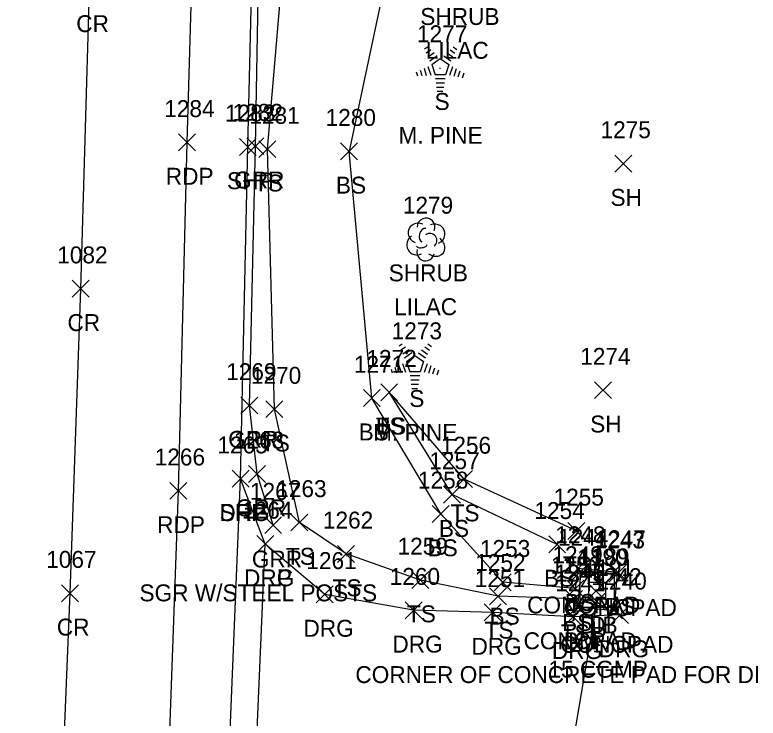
# Model space of a CAD drawing. Extents: x 1618262 to 1622220, y 273782 to 283685.
# Drawn here: x 1622055.1 to 1622142.9, y 282582.4 to 282665.6 of the extents above; entities that cross this region are included whole.
import ezdxf

# ---------------------------------------------------------------- set-up
doc = ezdxf.new("R2010")
doc.units = 0
for name, color, linetype in [('C_A', 7, 'Continuous'), ('C_C', 7, 'Continuous'), ('C_I', 7, 'Continuous'), ('CPBM', 7, 'Continuous'), ('D_A', 7, 'Continuous'), ('D_C', 7, 'Continuous'), ('D_I', 7, 'Continuous'), ('D_TIC', 7, 'Continuous'), ('DCP', 7, 'Continuous'), ('DS', 7, 'Continuous'), ('L_A', 7, 'Continuous'), ('L_C', 7, 'Continuous'), ('L_I', 7, 'Continuous'), ('L_TIC', 7, 'Continuous'), ('LELB', 7, 'Continuous'), ('LS', 7, 'Continuous'), ('LSH', 7, 'Continuous'), ('LTC', 7, 'Continuous'), ('P_A', 7, 'Continuous'), ('P_I', 7, 'Continuous'), ('P_TIC', 7, 'Continuous'), ('PET', 7, 'Continuous'), ('PRC', 7, 'Continuous'), ('PSP', 7, 'Continuous'), ('R_A', 7, 'Continuous'), ('R_C', 7, 'Continuous'), ('R_I', 7, 'Continuous'), ('R_TIC', 7, 'Continuous'), ('RDG', 7, 'Continuous'), ('RDP', 7, 'Continuous'), ('RGR', 7, 'Continuous')]:
    doc.layers.add(name, color=color, linetype=linetype)

msp = doc.modelspace()

# ---------------------------------------------------------------- linework, layer by layer
at = {"layer": 'CPBM'}
for p, q in [((1622121.111, 282595.082), (1622121.111, 282596.082)), ((1622121.111, 282596.082), (1622122.111, 282596.082)), ((1622121.614, 282595.582), (1622121.614, 282595.582)), ((1622121.614, 282595.582), (1622121.614, 282595.582)), ((1622122.111, 282596.082), (1622122.111, 282595.082)), ((1622122.111, 282595.082), (1622121.111, 282595.082))]:
    msp.add_line(p, q, dxfattribs=at)
at = {"layer": 'D_TIC'}
for points in [[(1622122.731, 282596.449), (1622124.731, 282598.449)], [(1622124.731, 282596.449), (1622122.731, 282598.449)], [(1622122.826, 282595.221), (1622124.826, 282597.221)], [(1622124.826, 282595.221), (1622122.826, 282597.221)]]:
    msp.add_lwpolyline(points, dxfattribs=at)
at = {"layer": 'DCP'}
msp.add_lwpolyline([(1622123.826, 282596.221), (1622105.825, 282490.473)], dxfattribs=at)
at = {"layer": 'DS'}
for p, q in [((1622121.872, 282599.503), (1622125.872, 282599.503)), ((1622121.872, 282595.503), (1622121.872, 282599.503)), ((1622125.872, 282599.503), (1622125.872, 282595.503)), ((1622122.872, 282596.503), (1622122.872, 282598.503)), ((1622122.872, 282598.503), (1622124.872, 282598.503)), ((1622124.872, 282598.503), (1622124.872, 282596.503)), ((1622123.877, 282597.504), (1622123.877, 282597.504)), ((1622123.877, 282597.504), (1622123.877, 282597.504)), ((1622124.872, 282596.503), (1622122.872, 282596.503)), ((1622125.872, 282595.503), (1622121.872, 282595.503))]:
    msp.add_line(p, q, dxfattribs=at)
at = {"layer": 'L_TIC'}
for points in [[(1622083.898, 282648.699), (1622085.898, 282650.699)], [(1622085.898, 282648.699), (1622083.898, 282650.699)], [(1622093.56, 282648.447), (1622095.56, 282650.447)], [(1622095.56, 282648.447), (1622093.56, 282650.447)], [(1622125.961, 282646.995), (1622127.961, 282648.995)], [(1622127.961, 282646.995), (1622125.961, 282648.995)], [(1622098.291, 282619.965), (1622100.291, 282621.965)], [(1622100.291, 282619.965), (1622098.291, 282621.965)], [(1622098.291, 282619.965), (1622100.291, 282621.965)], [(1622100.291, 282619.965), (1622098.291, 282621.965)], [(1622123.56, 282620.206), (1622125.56, 282622.206)], [(1622125.56, 282620.206), (1622123.56, 282622.206)], [(1622096.247, 282619.269), (1622098.247, 282621.269)], [(1622098.247, 282619.269), (1622096.247, 282621.269)], [(1622084.727, 282617.96), (1622086.727, 282619.96)], [(1622086.727, 282617.96), (1622084.727, 282619.96)], [(1622107.138, 282609.7), (1622109.138, 282611.7)], [(1622109.138, 282609.7), (1622107.138, 282611.7)], [(1622105.732, 282607.863), (1622107.732, 282609.863)], [(1622107.732, 282607.863), (1622105.732, 282609.863)], [(1622104.39, 282605.573), (1622106.39, 282607.573)], [(1622106.39, 282605.573), (1622104.39, 282607.573)], [(1622087.687, 282604.568), (1622089.687, 282606.568)], [(1622089.687, 282604.568), (1622087.687, 282606.568)], [(1622120.414, 282603.561), (1622122.414, 282605.561)], [(1622122.414, 282603.561), (1622120.414, 282605.561)], [(1622118.15, 282601.979), (1622120.15, 282603.979)], [(1622120.15, 282601.979), (1622118.15, 282603.979)], [(1622093.202, 282600.848), (1622095.202, 282602.848)], [(1622095.202, 282600.848), (1622093.202, 282602.848)], [(1622120.607, 282599.11), (1622122.607, 282601.11)], [(1622122.607, 282599.11), (1622120.607, 282601.11)], [(1622120.949, 282598.814), (1622122.949, 282600.814)], [(1622122.949, 282598.814), (1622120.949, 282600.814)], [(1622125.271, 282598.502), (1622127.271, 282600.502)], [(1622127.271, 282598.502), (1622125.271, 282600.502)], [(1622125.363, 282598.643), (1622127.363, 282600.643)], [(1622127.363, 282598.643), (1622125.363, 282600.643)], [(1622101.984, 282597.765), (1622103.984, 282599.765)], [(1622103.984, 282597.765), (1622101.984, 282599.765)], [(1622111.715, 282597.493), (1622113.715, 282599.493)], [(1622113.715, 282597.493), (1622111.715, 282599.493)], [(1622120.287, 282596.755), (1622122.287, 282598.755)], [(1622122.287, 282596.755), (1622120.287, 282598.755)], [(1622111.16, 282595.839), (1622113.16, 282597.839)], [(1622113.16, 282595.839), (1622111.16, 282597.839)], [(1622120.158, 282595.521), (1622122.158, 282597.521)], [(1622122.158, 282595.521), (1622120.158, 282597.521)], [(1622120.531, 282594.582), (1622122.531, 282596.582)], [(1622122.531, 282594.582), (1622120.531, 282596.582)], [(1622124.873, 282594.159), (1622126.873, 282596.159)], [(1622126.873, 282594.159), (1622124.873, 282596.159)]]:
    msp.add_lwpolyline(points, dxfattribs=at)
at = {"layer": 'LELB'}
for points in [[(1622121.158, 282596.521), (1622112.16, 282596.839), (1622102.984, 282598.765), (1622094.202, 282601.848), (1622088.687, 282605.568), (1622085.727, 282618.96), (1622084.898, 282649.699), (1622087.596, 282681.102), (1622086.983, 282710.968), (1622088.16, 282744.854), (1622088.43, 282782.064), (1622089.473, 282801.31), (1622094.579, 282809.136), (1622103.227, 282816.892), (1622109.052, 282823.895), (1622118.477, 282854.453), (1622116.353, 282881.374), (1622111.854, 282914.537), (1622109.182, 282938.553)], [(1622099.84, 282674.39), (1622094.56, 282649.447)], [(1622126.363, 282599.643), (1622121.607, 282600.11), (1622121.287, 282597.755), (1622112.715, 282598.493), (1622105.39, 282606.573), (1622097.247, 282620.269), (1622094.56, 282649.447)], [(1622119.15, 282602.979), (1622106.732, 282608.863), (1622099.291, 282620.965)], [(1622121.414, 282604.561), (1622108.138, 282610.7), (1622099.291, 282620.965)]]:
    msp.add_lwpolyline(points, dxfattribs=at)
at = {"layer": 'LS'}
msp.add_lwpolyline([(1622125.873, 282595.159), (1622126.271, 282599.502), (1622121.949, 282599.814), (1622121.531, 282595.582), (1622125.873, 282595.159)], dxfattribs=at)
at = {"layer": 'LSH'}
msp.add_line((1622103.607, 282639.075), (1622103.607, 282639.075), dxfattribs=at)
msp.add_line((1622103.607, 282639.075), (1622103.607, 282639.075), dxfattribs=at)
msp.add_arc((1622103.654, 282640.509), 1.047, 335.52715, 180.95627, dxfattribs=at)
for centre, major_axis, ratio, start_param, end_param in [((1622102.816, 282639.741), (1.21, -0.512), 0.895232, 1.570796, 4.712389), ((1622103.399, 282639.533), (-0.208, -0.792), 0.645439, 3.141593, 6.283185), ((1622104.649, 282639.658), (-1.141, -0.483), 0.949671, 1.570796, 4.712389), ((1622102.524, 282638.366), (0.584, -1.042), 0.959034, 3.141593, 6.283185), ((1622104.107, 282638.908), (-0.5, 0.667), 0.989748, 3.141593, 6.283185), ((1622104.608, 282638.242), (-1.09, 0.792), 0.841452, 1.570796, 4.712389), ((1622103.608, 282637.575), (0.265, 1.061), 0.942809, 1.570796, 4.712389), ((1622103.149, 282638.325), (-0.625, -0.083), 0.423636, 0, 3.141593)]:
    msp.add_ellipse(centre, major_axis=major_axis, ratio=ratio, start_param=start_param, end_param=end_param, dxfattribs=at)
at = {"layer": 'LTC'}
for p, q in [((1622103.47, 282661.546), (1622103.824, 282661.803)), ((1622103.679, 282661.08), (1622104.208, 282661.464)), ((1622106.497, 282661.438), (1622107.046, 282661.039)), ((1622106.868, 282661.786), (1622107.287, 282661.482)), ((1622103.889, 282660.614), (1622104.592, 282661.126)), ((1622104.098, 282660.149), (1622104.977, 282660.787)), ((1622104.323, 282659.694), (1622105.335, 282660.428)), ((1622105.335, 282660.428), (1622106.332, 282659.703)), ((1622105.755, 282660.741), (1622106.564, 282660.152)), ((1622106.126, 282661.089), (1622106.805, 282660.596)), ((1622104.323, 282659.694), (1622104.71, 282658.5)), ((1622106.332, 282659.703), (1622105.94, 282658.5)), ((1622102.502, 282658.825), (1622102.654, 282658.357)), ((1622102.957, 282659.042), (1622103.169, 282658.39)), ((1622103.413, 282659.258), (1622103.684, 282658.423)), ((1622103.868, 282659.474), (1622104.199, 282658.455)), ((1622106.769, 282659.432), (1622106.431, 282658.393)), ((1622107.214, 282659.182), (1622106.926, 282658.297)), ((1622107.658, 282658.932), (1622107.421, 282658.202)), ((1622108.102, 282658.682), (1622107.916, 282658.107)), ((1622105.94, 282658.5), (1622104.71, 282658.5)), ((1622105.902, 282658), (1622104.757, 282658)), ((1622105.818, 282657.5), (1622104.83, 282657.5)), ((1622105.735, 282657), (1622104.903, 282657)), ((1622105.651, 282656.5), (1622104.976, 282656.5)), ((1622100.477, 282626.431), (1622100.832, 282626.688)), ((1622100.687, 282625.965), (1622101.216, 282626.35)), ((1622103.504, 282626.323), (1622104.054, 282625.924)), ((1622103.876, 282626.671), (1622104.295, 282626.367)), ((1622100.897, 282625.5), (1622101.6, 282626.011)), ((1622101.106, 282625.034), (1622101.984, 282625.672)), ((1622101.331, 282624.579), (1622102.342, 282625.313)), ((1622102.342, 282625.313), (1622103.339, 282624.588)), ((1622102.762, 282625.626), (1622103.572, 282625.037)), ((1622103.134, 282625.975), (1622103.813, 282625.481)), ((1622101.331, 282624.579), (1622101.718, 282623.385)), ((1622103.339, 282624.588), (1622102.948, 282623.385)), ((1622099.51, 282623.71), (1622099.662, 282623.242)), ((1622099.965, 282623.927), (1622100.177, 282623.275)), ((1622100.421, 282624.143), (1622100.692, 282623.308)), ((1622100.876, 282624.36), (1622101.207, 282623.34)), ((1622103.777, 282624.317), (1622103.439, 282623.278)), ((1622104.222, 282624.067), (1622103.934, 282623.182)), ((1622104.666, 282623.817), (1622104.429, 282623.087)), ((1622105.11, 282623.567), (1622104.924, 282622.992)), ((1622102.948, 282623.385), (1622101.718, 282623.385)), ((1622102.91, 282622.885), (1622101.765, 282622.885)), ((1622102.826, 282622.385), (1622101.838, 282622.385)), ((1622102.742, 282621.885), (1622101.911, 282621.885)), ((1622102.659, 282621.385), (1622101.984, 282621.385))]:
    msp.add_line(p, q, dxfattribs=at)
at = {"layer": 'P_TIC'}
for points in [[(1622074.404, 282649.493), (1622076.404, 282651.493)], [(1622076.404, 282649.493), (1622074.404, 282651.493)], [(1622081.589, 282648.97), (1622083.589, 282650.97)], [(1622083.589, 282648.97), (1622081.589, 282650.97)], [(1622061.841, 282632.199), (1622063.841, 282634.199)], [(1622063.841, 282632.199), (1622061.841, 282634.199)], [(1622080.734, 282609.733), (1622082.734, 282611.733)], [(1622082.734, 282609.733), (1622080.734, 282611.733)], [(1622073.383, 282608.306), (1622075.383, 282610.306)], [(1622075.383, 282608.306), (1622073.383, 282610.306)], [(1622060.585, 282596.203), (1622062.585, 282598.203)], [(1622062.585, 282596.203), (1622060.585, 282598.203)]]:
    msp.add_lwpolyline(points, dxfattribs=at)
at = {"layer": 'PET'}
msp.add_lwpolyline([(1622055.389, 282357.789), (1622060.735, 282405.546), (1622064, 282439.097), (1622067.385, 282476.749), (1622069.453, 282501.975), (1622071.171, 282531.215), (1622072.586, 282558.991), (1622074.383, 282609.306), (1622075.404, 282650.493), (1622076.38, 282682.885), (1622076.73, 282709.495), (1622076.466, 282742.794), (1622075.649, 282781.747), (1622073.854, 282831.38), (1622072.41, 282861.117), (1622070.969, 282880.709), (1622069.108, 282909.864), (1622067.074, 282934.336)], dxfattribs=at)
at = {"layer": 'PRC'}
msp.add_lwpolyline([(1622043.286, 282360.387), (1622048.896, 282407.643), (1622051.69, 282440.973), (1622055.31, 282477.626), (1622057.865, 282516.742), (1622059.99, 282557.513), (1622061.585, 282597.203), (1622062.841, 282633.199), (1622063.878, 282668.538), (1622064.406, 282708.38), (1622064.503, 282747.028), (1622063.87, 282768.185), (1622062.59, 282807.537), (1622060.956, 282848.034), (1622058.907, 282883.676), (1622055.26, 282933.108)], dxfattribs=at)
at = {"layer": 'PSP'}
msp.add_lwpolyline([(1622063.899, 282356.417), (1622068.955, 282404.452), (1622072.02, 282437.728), (1622074.665, 282475.613), (1622076.635, 282501.43), (1622078.271, 282531.064), (1622079.381, 282546.297), (1622079.58, 282558.785), (1622081.734, 282610.733), (1622082.589, 282649.97), (1622083.395, 282682.719), (1622083.739, 282709.962), (1622083.621, 282744.119), (1622083.448, 282781.355), (1622083.165, 282811.548), (1622082.701, 282831.314), (1622081.46, 282858.351), (1622080.359, 282881.435), (1622078.26, 282910.946), (1622077.134, 282929.735), (1622076.71, 282935.514)], dxfattribs=at)
at = {"layer": 'R_TIC'}
for points in [[(1622082.481, 282649.056), (1622084.481, 282651.056)], [(1622084.481, 282649.056), (1622082.481, 282651.056)], [(1622081.779, 282618.397), (1622083.779, 282620.397)], [(1622083.779, 282618.397), (1622081.779, 282620.397)], [(1622082.68, 282610.3), (1622084.68, 282612.3)], [(1622084.68, 282610.3), (1622082.68, 282612.3)], [(1622080.734, 282609.733), (1622082.734, 282611.733)], [(1622082.734, 282609.733), (1622080.734, 282611.733)], [(1622084.58, 282604.247), (1622086.58, 282606.247)], [(1622086.58, 282604.247), (1622084.58, 282606.247)], [(1622083.651, 282602.022), (1622085.651, 282604.022)], [(1622085.651, 282602.022), (1622083.651, 282604.022)], [(1622083.651, 282602.022), (1622085.651, 282604.022)], [(1622085.651, 282602.022), (1622083.651, 282604.022)], [(1622090.679, 282596.059), (1622092.679, 282598.059)], [(1622092.679, 282596.059), (1622090.679, 282598.059)], [(1622101.188, 282594.189), (1622103.188, 282596.189)], [(1622103.188, 282594.189), (1622101.188, 282596.189)], [(1622110.535, 282593.93), (1622112.535, 282595.93)], [(1622112.535, 282593.93), (1622110.535, 282595.93)], [(1622120.042, 282593.428), (1622122.042, 282595.428)], [(1622122.042, 282593.428), (1622120.042, 282595.428)], [(1622125.565, 282593.637), (1622127.565, 282595.637)], [(1622127.565, 282593.637), (1622125.565, 282595.637)]]:
    msp.add_lwpolyline(points, dxfattribs=at)
at = {"layer": 'RDG'}
msp.add_lwpolyline([(1622126.565, 282594.637), (1622121.042, 282594.428), (1622111.535, 282594.93), (1622102.188, 282595.189), (1622091.679, 282597.059), (1622084.651, 282603.022), (1622081.734, 282610.733)], dxfattribs=at)
at = {"layer": 'RDP'}
msp.add_lwpolyline([(1622079.381, 282546.297), (1622082.212, 282549.998), (1622082.715, 282558.142), (1622084.651, 282603.022)], dxfattribs=at)
at = {"layer": 'RGR'}
msp.add_lwpolyline([(1622085.58, 282605.247), (1622083.68, 282611.3), (1622082.779, 282619.397), (1622083.481, 282650.056), (1622084.103, 282682.868), (1622084.658, 282710.116), (1622084.362, 282744.316), (1622084.303, 282781.106), (1622084.959, 282794.061), (1622087.053, 282807.794)], dxfattribs=at)

# ---------------------------------------------------------------- texts
at = {"layer": 'C_A'}
msp.add_text('BM', height=2, dxfattribs=at).set_placement((1622119.929, 282590.582))
at = {"layer": 'C_C'}
msp.add_text('CORNER OF CONCRETE PAD FOR DI', height=2, dxfattribs=at).set_placement((1622095.299, 282586.582))
at = {"layer": 'C_I'}
msp.add_text('1246', height=2, dxfattribs=at).set_placement((1622118.866, 282598.582))
at = {"layer": 'D_A'}
for s, p in [('DIB', (1622121.834, 282592.449)), ('DI', (1622122.932, 282592.504)), ('P', (1622123.204, 282591.221))]:
    msp.add_text(s, height=2, dxfattribs=at).set_placement(p)
at = {"layer": 'D_C'}
msp.add_text('15 CGMP', height=2, dxfattribs=at).set_placement((1622118.118, 282587.221))
at = {"layer": 'D_I'}
for s, p in [('1190', (1622121.519, 282600.449)), ('1189', (1622121.744, 282600.504)), ('1191', (1622122.267, 282599.221))]:
    msp.add_text(s, height=2, dxfattribs=at).set_placement(p)
at = {"layer": 'L_A'}
for s, p in [('SHRUB', (1622102.973, 282664.384)), ('S', (1622104.66, 282654.338)), ('TS', (1622083.307, 282644.699)), ('BS', (1622093, 282644.447)), ('SH', (1622125.449, 282642.995)), ('SHRUB', (1622099.237, 282634.075)), ('S', (1622101.668, 282619.223)), ('TS', (1622097.7, 282615.965)), ('BS', (1622097.732, 282615.965)), ('SH', (1622123.049, 282616.206)), ('BS', (1622095.688, 282615.269)), ('TS', (1622084.137, 282613.96)), ('TS', (1622106.548, 282605.7)), ('BS', (1622105.173, 282603.863)), ('BS', (1622103.831, 282601.573)), ('TS', (1622087.096, 282600.568)), ('TS', (1622119.823, 282599.561)), ('BS', (1622117.591, 282597.979)), ('TS', (1622092.611, 282596.848)), ('CONCPAD', (1622115.595, 282594.814)), ('CONCPAD', (1622119.917, 282594.502)), ('BS', (1622120.048, 282595.11)), ('BS', (1622124.804, 282594.643)), ('TS', (1622101.394, 282593.765)), ('BS', (1622111.156, 282593.493)), ('BS', (1622119.728, 282592.755)), ('TS', (1622110.57, 282591.839)), ('TS', (1622119.568, 282591.521)), ('CONCPAD', (1622115.176, 282590.582)), ('CONCPAD', (1622119.519, 282590.159))]:
    msp.add_text(s, height=2, dxfattribs=at).set_placement(p)
at = {"layer": 'L_C'}
for s, p in [('LILAC', (1622103.619, 282660.384)), ('M. PINE', (1622100.393, 282650.338)), ('LILAC', (1622099.883, 282630.075)), ('M. PINE', (1622097.401, 282615.223))]:
    msp.add_text(s, height=2, dxfattribs=at).set_placement(p)
at = {"layer": 'L_I'}
for s, p in [('1277', (1622102.582, 282662.338)), ('1281', (1622082.772, 282652.699)), ('1280', (1622091.78, 282652.447)), ('1275', (1622124.268, 282650.995)), ('1279', (1622100.907, 282642.075)), ('1273', (1622099.59, 282627.223)), ('1274', (1622121.868, 282624.206)), ('1271', (1622095.121, 282623.269)), ('1272', (1622096.598, 282623.965)), ('1272', (1622096.598, 282623.965)), ('1270', (1622082.948, 282621.96)), ('1256', (1622105.39, 282613.7)), ('1257', (1622104.039, 282611.863)), ('1258', (1622102.698, 282609.573)), ('1263', (1622085.947, 282608.568)), ('1255', (1622118.721, 282607.561)), ('1254', (1622116.457, 282605.979)), ('1262', (1622091.462, 282604.848)), ('1248', (1622118.915, 282603.11)), ('1244', (1622119.256, 282602.814)), ('1243', (1622123.579, 282602.502)), ('1247', (1622123.67, 282602.643)), ('1259', (1622100.284, 282601.765)), ('1253', (1622110.022, 282601.493)), ('1249', (1622118.587, 282600.755)), ('1252', (1622109.467, 282599.839)), ('1250', (1622118.379, 282599.521)), ('1245', (1622118.838, 282598.582)), ('1242', (1622123.181, 282598.159))]:
    msp.add_text(s, height=2, dxfattribs=at).set_placement(p)
at = {"layer": 'LTC'}
for p in [(1622105.217, 282659.442), (1622102.225, 282624.327)]:
    msp.add_text('.', height=1.037, rotation=270, dxfattribs=at).set_placement(p)
at = {"layer": 'P_A'}
for s, p in [('CR', (1622062.311, 282663.538)), ('RDP', (1622072.892, 282645.493)), ('SHP', (1622080.125, 282644.97)), ('CR', (1622061.274, 282628.199)), ('SHP', (1622079.269, 282605.733)), ('RDP', (1622071.871, 282604.306)), ('CR', (1622060.018, 282592.203))]:
    msp.add_text(s, height=2, dxfattribs=at).set_placement(p)
at = {"layer": 'P_I'}
for s, p in [('1284', (1622072.712, 282653.493)), ('1283', (1622079.896, 282652.97)), ('1082', (1622060.07, 282636.199)), ('1265', (1622078.994, 282613.733)), ('1266', (1622071.588, 282612.306)), ('1067', (1622058.766, 282600.203))]:
    msp.add_text(s, height=2, dxfattribs=at).set_placement(p)
at = {"layer": 'R_A'}
for s, p in [('GRR', (1622080.969, 282645.056)), ('GRR', (1622080.267, 282614.397)), ('DRG', (1622079.222, 282605.733)), ('GRR', (1622081.169, 282606.3)), ('GRR', (1622083.068, 282600.247)), ('DRG', (1622082.14, 282598.022)), ('DRP', (1622082.14, 282598.022)), ('DRG', (1622089.167, 282592.059)), ('DRG', (1622099.676, 282590.189)), ('DRG', (1622109.023, 282589.93)), ('DRG', (1622118.53, 282589.428)), ('DRG', (1622124.053, 282589.637))]:
    msp.add_text(s, height=2, dxfattribs=at).set_placement(p)
at = {"layer": 'R_C'}
msp.add_text('SGR W/STEEL POSTS', height=2, dxfattribs=at).set_placement((1622069.785, 282596.247))
at = {"layer": 'R_I'}
for s, p in [('1282', (1622080.789, 282653.056)), ('1269', (1622080.031, 282622.397)), ('1265', (1622078.994, 282613.733)), ('1268', (1622080.94, 282614.3)), ('1267', (1622082.84, 282608.247)), ('1264', (1622081.911, 282606.022)), ('1264', (1622081.911, 282606.022)), ('1261', (1622089.506, 282600.059)), ('1260', (1622099.361, 282598.189)), ('1251', (1622109.409, 282597.93)), ('1241', (1622118.916, 282597.428)), ('1240', (1622123.786, 282597.637))]:
    msp.add_text(s, height=2, dxfattribs=at).set_placement(p)

doc.saveas('drawing.dxf')
